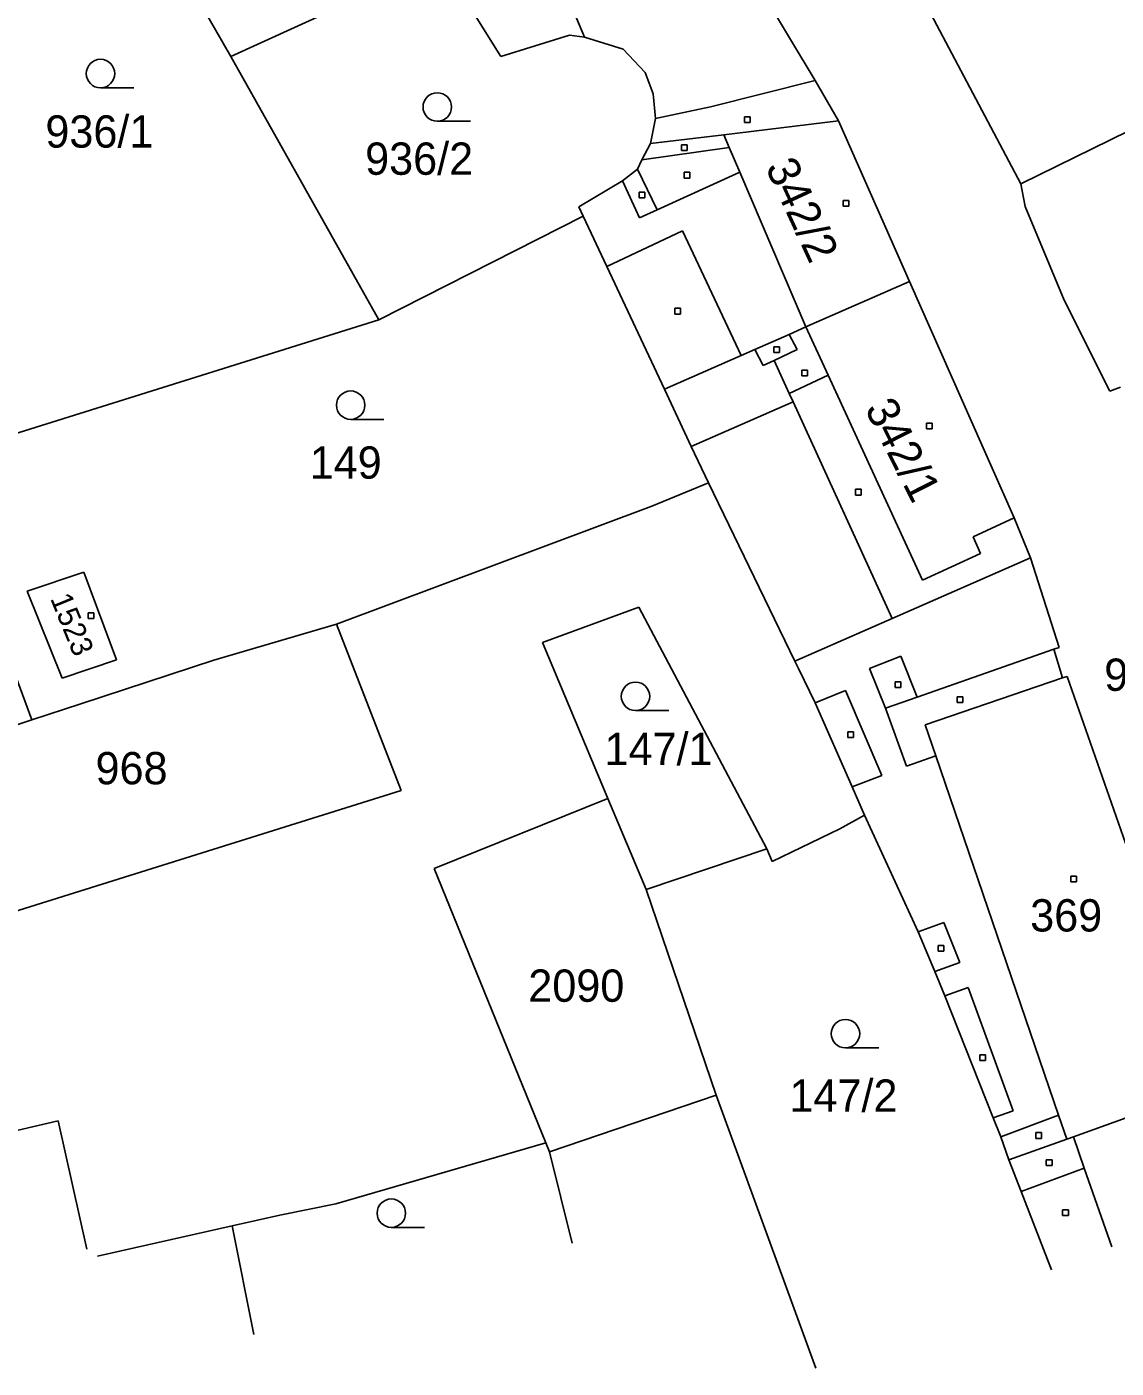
# Model space of a CAD drawing. Extents: x -711879 to -711361, y -1048782 to -1048177.
# Drawn here: x -711759.4 to -711702.1, y -1048728.8 to -1048658.1 of the extents above; entities that cross this region are included whole.
import ezdxf

# ---------------------------------------------------------------- set-up
doc = ezdxf.new("R2010")
doc.units = 0
for name, color, linetype in [('Vrstva 1', 7, 'Continuous'), ('Vrstva 14', 7, 'Continuous'), ('Vrstva 15', 7, 'Continuous'), ('Vrstva 2', 7, 'Continuous'), ('Vrstva 23', 7, 'Continuous'), ('Vrstva 25', 7, 'Continuous'), ('Vrstva 46', 7, 'Continuous')]:
    doc.layers.add(name, color=color, linetype=linetype)

msp = doc.modelspace()

# ---------------------------------------------------------------- linework, layer by layer
at = {"layer": 'Vrstva 1'}
for p, q in [((-711647.12, -1048637.04), (-711707.08, -1048666.39)), ((-711748.69, -1048659.7), (-711756.32, -1048646.29)), ((-711737.61, -1048654.63), (-711748.69, -1048659.7)), ((-711737.61, -1048654.63), (-711734.47, -1048659.69)), ((-711722.03, -1048654.1), (-711717.9, -1048660.95)), ((-711707.08, -1048666.39), (-711712.77, -1048655.63)), ((-711734.47, -1048659.69), (-711730.85, -1048658.57)), ((-711730.85, -1048658.57), (-711730.06, -1048658.68)), ((-711728.02, -1048659.31), (-711730.06, -1048658.68)), ((-711726.86, -1048660.53), (-711728.02, -1048659.31)), ((-711748.69, -1048659.7), (-711740.88, -1048673.56)), ((-711726.43, -1048661.65), (-711726.86, -1048660.53)), ((-711717.9, -1048660.95), (-711716.67, -1048663.08)), ((-711726.32, -1048662.96), (-711726.43, -1048661.65)), ((-711726.58, -1048664.28), (-711726.32, -1048662.96)), ((-711716.67, -1048663.08), (-711722.72, -1048663.81)), ((-711716.67, -1048663.08), (-711712.94, -1048671.54)), ((-711722.72, -1048663.81), (-711726.58, -1048664.28)), ((-711727.03, -1048665.13), (-711726.58, -1048664.28)), ((-711727.26, -1048665.62), (-711727.03, -1048665.13)), ((-711728.06, -1048666.24), (-711727.26, -1048665.62)), ((-711730.35, -1048667.6), (-711728.06, -1048666.24)), ((-711706.84, -1048667.59), (-711707.08, -1048666.39)), ((-711730.12, -1048668.09), (-711740.88, -1048673.56)), ((-711730.12, -1048668.09), (-711730.35, -1048667.6)), ((-711730.12, -1048668.09), (-711728.88, -1048670.74)), ((-711704.79, -1048672.52), (-711706.84, -1048667.59)), ((-711728.88, -1048670.74), (-711725.85, -1048677.2)), ((-711718.39, -1048673.93), (-711712.94, -1048671.54)), ((-711712.94, -1048671.54), (-711707.43, -1048683.98)), ((-711702.39, -1048677.31), (-711704.79, -1048672.52)), ((-711761.8, -1048680.11), (-711740.88, -1048673.56)), ((-711721.09, -1048675.12), (-711719.27, -1048674.32)), ((-711719.27, -1048674.32), (-711718.39, -1048673.93)), ((-711721.81, -1048675.44), (-711721.09, -1048675.12)), ((-711725.85, -1048677.2), (-711721.81, -1048675.44)), ((-711724.43, -1048680.23), (-711725.85, -1048677.2)), ((-711701.82, -1048677.11), (-711702.39, -1048677.31)), ((-711723.53, -1048682.13), (-711724.43, -1048680.23)), ((-711723.53, -1048682.13), (-711726.51, -1048683.36)), ((-711718.98, -1048691.53), (-711723.53, -1048682.13)), ((-711763.42, -1048683.16), (-711759.16, -1048694.62)), ((-711743.11, -1048689.58), (-711726.51, -1048683.36)), ((-711707.43, -1048683.98), (-711706.56, -1048686.09)), ((-711713.85, -1048689.28), (-711706.56, -1048686.09)), ((-711706.56, -1048686.09), (-711705.05, -1048690.8)), ((-711756.42, -1048686.85), (-711759.41, -1048687.84)), ((-711754.71, -1048691.46), (-711756.42, -1048686.85)), ((-711757.57, -1048692.43), (-711759.41, -1048687.84)), ((-711727.2, -1048688.68), (-711732.27, -1048690.54)), ((-711720.45, -1048701.4), (-711727.2, -1048688.68)), ((-711718.98, -1048691.53), (-711713.85, -1048689.28)), ((-711743.11, -1048689.58), (-711749.58, -1048691.48)), ((-711743.11, -1048689.58), (-711739.72, -1048698.33)), ((-711728.82, -1048698.75), (-711732.27, -1048690.54)), ((-711757.57, -1048692.43), (-711754.71, -1048691.46)), ((-711705.05, -1048690.8), (-711705.33, -1048690.9)), ((-711704.88, -1048692.41), (-711705.33, -1048690.9)), ((-711749.58, -1048691.48), (-711756.58, -1048693.78)), ((-711718.98, -1048691.53), (-711718.79, -1048691.92)), ((-711718.79, -1048691.92), (-711717.91, -1048693.72)), ((-711704.64, -1048692.33), (-711704.88, -1048692.41)), ((-711697.07, -1048713.95), (-711704.64, -1048692.33)), ((-711759.16, -1048694.62), (-711756.58, -1048693.78)), ((-711717.91, -1048693.72), (-711715.96, -1048698.15)), ((-711761.13, -1048695.26), (-711759.16, -1048694.62)), ((-711739.72, -1048698.33), (-711764.36, -1048706.06)), ((-711715.96, -1048698.15), (-711715.31, -1048699.64)), ((-711728.82, -1048698.75), (-711737.97, -1048702.44)), ((-711726.8, -1048703.55), (-711728.82, -1048698.75)), ((-711716.6, -1048700.35), (-711715.31, -1048699.64)), ((-711715.31, -1048699.64), (-711712.48, -1048705.78)), ((-711720.17, -1048702.07), (-711716.6, -1048700.35)), ((-711720.45, -1048701.4), (-711726.8, -1048703.55)), ((-711720.45, -1048701.4), (-711720.17, -1048702.07)), ((-711737.97, -1048702.44), (-711732.1, -1048716.88)), ((-711723.12, -1048714.37), (-711726.8, -1048703.55)), ((-711712.48, -1048705.78), (-711711.6, -1048707.86)), ((-711711.6, -1048707.86), (-711711.07, -1048709.14)), ((-711711.07, -1048709.14), (-711708.53, -1048715.57)), ((-711697.07, -1048713.95), (-711704.3, -1048716.57)), ((-711723.12, -1048714.37), (-711731.9, -1048717.36)), ((-711723.12, -1048714.37), (-711717.87, -1048728.75)), ((-711708.53, -1048715.57), (-711708.12, -1048716.57)), ((-711732.1, -1048716.88), (-711743.15, -1048720.09)), ((-711732.1, -1048716.88), (-711731.9, -1048717.36)), ((-711708.12, -1048716.57), (-711707.7, -1048717.78)), ((-711704.65, -1048716.69), (-711707.7, -1048717.78)), ((-711704.3, -1048716.57), (-711704.65, -1048716.69)), ((-711731.9, -1048717.36), (-711730.71, -1048722.16)), ((-711707.7, -1048717.78), (-711707.06, -1048719.44)), ((-711707.06, -1048719.44), (-711705.46, -1048723.58)), ((-711743.15, -1048720.09), (-711746.1, -1048720.7)), ((-711746.1, -1048720.7), (-711748.62, -1048721.26)), ((-711748.62, -1048721.26), (-711755.7, -1048722.85)), ((-711747.48, -1048726.98), (-711748.62, -1048721.26))]:
    msp.add_line(p, q, dxfattribs=at)
at = {"layer": 'Vrstva 2'}
for p, q in [((-711730.06, -1048658.68), (-711734.14, -1048648.9)), ((-711717.9, -1048660.95), (-711723.41, -1048662.34)), ((-711723.41, -1048662.34), (-711726.32, -1048662.96)), ((-711722.43, -1048664.48), (-711722.72, -1048663.81)), ((-711727.03, -1048665.13), (-711722.43, -1048664.48)), ((-711721.87, -1048665.79), (-711722.43, -1048664.48)), ((-711727.26, -1048665.62), (-711726.23, -1048667.77)), ((-711721.87, -1048665.79), (-711726.23, -1048667.77)), ((-711718.39, -1048673.93), (-711721.87, -1048665.79)), ((-711727.15, -1048668.19), (-711728.06, -1048666.24)), ((-711726.23, -1048667.77), (-711727.15, -1048668.19)), ((-711724.89, -1048668.87), (-711728.88, -1048670.74)), ((-711721.81, -1048675.44), (-711724.89, -1048668.87)), ((-711718.86, -1048675.12), (-711719.27, -1048674.32)), ((-711717.22, -1048676.47), (-711718.39, -1048673.93)), ((-711721.09, -1048675.12), (-711720.65, -1048675.96)), ((-711720.06, -1048675.69), (-711718.86, -1048675.12)), ((-711720.65, -1048675.96), (-711720.06, -1048675.69)), ((-711719.27, -1048677.44), (-711720.06, -1048675.69)), ((-711719.27, -1048677.44), (-711717.22, -1048676.47)), ((-711717.22, -1048676.47), (-711712.25, -1048687.26)), ((-711719.07, -1048677.87), (-711724.43, -1048680.23)), ((-711719.07, -1048677.87), (-711719.27, -1048677.44)), ((-711713.85, -1048689.28), (-711719.07, -1048677.87)), ((-711707.43, -1048683.98), (-711709.59, -1048684.98)), ((-711709.59, -1048684.98), (-711709.2, -1048685.86)), ((-711709.2, -1048685.86), (-711712.25, -1048687.26)), ((-711715.04, -1048691.92), (-711713.4, -1048691.27)), ((-711713.4, -1048691.27), (-711712.53, -1048693.42)), ((-711712.53, -1048693.42), (-711705.33, -1048690.9)), ((-711714.2, -1048694.01), (-711715.04, -1048691.92)), ((-711704.88, -1048692.41), (-711712.11, -1048694.88)), ((-711716.31, -1048693.07), (-711717.91, -1048693.72)), ((-711716.31, -1048693.07), (-711714.4, -1048697.54)), ((-711714.2, -1048694.01), (-711712.53, -1048693.42)), ((-711714.2, -1048694.01), (-711713.09, -1048697.06)), ((-711712.11, -1048694.88), (-711711.55, -1048696.51)), ((-711713.09, -1048697.06), (-711711.55, -1048696.51)), ((-711711.55, -1048696.51), (-711705.08, -1048715.43)), ((-711715.96, -1048698.15), (-711714.4, -1048697.54)), ((-711712.48, -1048705.78), (-711711.12, -1048705.29)), ((-711711.12, -1048705.29), (-711710.28, -1048707.39)), ((-711711.6, -1048707.86), (-711710.28, -1048707.39)), ((-711711.07, -1048709.14), (-711709.84, -1048708.71)), ((-711707.47, -1048715.21), (-711709.84, -1048708.71)), ((-711708.53, -1048715.57), (-711707.47, -1048715.21)), ((-711708.12, -1048716.57), (-711705.08, -1048715.43)), ((-711705.08, -1048715.43), (-711704.65, -1048716.69)), ((-711770.07, -1048718.6), (-711757.78, -1048715.73)), ((-711757.78, -1048715.73), (-711756.27, -1048722.49)), ((-711704.3, -1048716.57), (-711703.73, -1048718.22)), ((-711707.06, -1048719.44), (-711703.73, -1048718.22)), ((-711703.73, -1048718.22), (-711702.28, -1048722.36))]:
    msp.add_line(p, q, dxfattribs=at)
at = {"layer": 'Vrstva 23'}
for p, q in [((-711755.55, -1048661.34), (-711753.8, -1048661.34)), ((-711737.81, -1048663.1), (-711736.06, -1048663.1)), ((-711742.37, -1048678.8), (-711740.62, -1048678.8)), ((-711727.37, -1048694.13), (-711725.62, -1048694.13)), ((-711716.31, -1048711.89), (-711714.56, -1048711.89)), ((-711740.23, -1048721.34), (-711738.48, -1048721.34))]:
    msp.add_line(p, q, dxfattribs=at)
for centre in [(-711755.55, -1048660.59), (-711737.81, -1048662.35), (-711742.37, -1048678.05), (-711727.37, -1048693.38), (-711716.31, -1048711.14), (-711740.23, -1048720.59)]:
    msp.add_circle(centre, 0.75, dxfattribs=at)
at = {"layer": 'Vrstva 25'}
for p, q in [((-711721.63, -1048662.86), (-711721.33, -1048662.86)), ((-711721.63, -1048663.16), (-711721.63, -1048662.86)), ((-711721.33, -1048663.16), (-711721.63, -1048663.16)), ((-711721.33, -1048662.86), (-711721.33, -1048663.16)), ((-711724.95, -1048664.34), (-711724.65, -1048664.34)), ((-711724.95, -1048664.64), (-711724.95, -1048664.34)), ((-711724.65, -1048664.34), (-711724.65, -1048664.64)), ((-711724.65, -1048664.64), (-711724.95, -1048664.64)), ((-711724.81, -1048665.79), (-711724.51, -1048665.79)), ((-711724.81, -1048666.09), (-711724.81, -1048665.79)), ((-711724.51, -1048665.79), (-711724.51, -1048666.09)), ((-711724.51, -1048666.09), (-711724.81, -1048666.09)), ((-711727.18, -1048666.83), (-711726.88, -1048666.83)), ((-711727.18, -1048667.13), (-711727.18, -1048666.83)), ((-711726.88, -1048667.13), (-711727.18, -1048667.13)), ((-711726.88, -1048666.83), (-711726.88, -1048667.13)), ((-711716.43, -1048667.28), (-711716.13, -1048667.28)), ((-711716.43, -1048667.58), (-711716.43, -1048667.28)), ((-711716.13, -1048667.28), (-711716.13, -1048667.58)), ((-711716.13, -1048667.58), (-711716.43, -1048667.58)), ((-711725.29, -1048672.95), (-711724.99, -1048672.95)), ((-711725.29, -1048673.25), (-711725.29, -1048672.95)), ((-711724.99, -1048672.95), (-711724.99, -1048673.25)), ((-711724.99, -1048673.25), (-711725.29, -1048673.25)), ((-711720.09, -1048674.98), (-711719.79, -1048674.98)), ((-711720.09, -1048675.28), (-711720.09, -1048674.98)), ((-711719.79, -1048674.98), (-711719.79, -1048675.28)), ((-711719.79, -1048675.28), (-711720.09, -1048675.28)), ((-711718.61, -1048676.21), (-711718.31, -1048676.21)), ((-711718.61, -1048676.51), (-711718.61, -1048676.21)), ((-711718.31, -1048676.51), (-711718.61, -1048676.51)), ((-711718.31, -1048676.21), (-711718.31, -1048676.51)), ((-711712.05, -1048679), (-711711.75, -1048679)), ((-711712.05, -1048679.3), (-711712.05, -1048679)), ((-711711.75, -1048679.3), (-711712.05, -1048679.3)), ((-711711.75, -1048679), (-711711.75, -1048679.3)), ((-711715.78, -1048682.48), (-711715.48, -1048682.48)), ((-711715.78, -1048682.78), (-711715.78, -1048682.48)), ((-711715.48, -1048682.78), (-711715.78, -1048682.78)), ((-711715.48, -1048682.48), (-711715.48, -1048682.78)), ((-711756.2, -1048688.98), (-711755.9, -1048688.98)), ((-711756.2, -1048689.28), (-711756.2, -1048688.98)), ((-711755.9, -1048689.28), (-711756.2, -1048689.28)), ((-711755.9, -1048688.98), (-711755.9, -1048689.28)), ((-711713.7, -1048692.62), (-711713.4, -1048692.62)), ((-711713.7, -1048692.92), (-711713.7, -1048692.62)), ((-711713.4, -1048692.62), (-711713.4, -1048692.92)), ((-711713.4, -1048692.92), (-711713.7, -1048692.92)), ((-711710.43, -1048693.41), (-711710.13, -1048693.41)), ((-711710.43, -1048693.71), (-711710.43, -1048693.41)), ((-711710.13, -1048693.41), (-711710.13, -1048693.71)), ((-711710.13, -1048693.71), (-711710.43, -1048693.71)), ((-711716.18, -1048695.25), (-711715.88, -1048695.25)), ((-711716.18, -1048695.55), (-711716.18, -1048695.25)), ((-711715.88, -1048695.55), (-711716.18, -1048695.55)), ((-711715.88, -1048695.25), (-711715.88, -1048695.55)), ((-711704.44, -1048702.84), (-711704.14, -1048702.84)), ((-711704.44, -1048703.14), (-711704.44, -1048702.84)), ((-711704.14, -1048703.14), (-711704.44, -1048703.14)), ((-711704.14, -1048702.84), (-711704.14, -1048703.14)), ((-711711.42, -1048706.5), (-711711.12, -1048706.5)), ((-711711.42, -1048706.8), (-711711.42, -1048706.5)), ((-711711.12, -1048706.8), (-711711.42, -1048706.8)), ((-711711.12, -1048706.5), (-711711.12, -1048706.8)), ((-711709.24, -1048712.26), (-711708.94, -1048712.26)), ((-711709.24, -1048712.56), (-711709.24, -1048712.26)), ((-711708.94, -1048712.56), (-711709.24, -1048712.56)), ((-711708.94, -1048712.26), (-711708.94, -1048712.56)), ((-711706.28, -1048716.35), (-711705.98, -1048716.35)), ((-711706.28, -1048716.65), (-711706.28, -1048716.35)), ((-711705.98, -1048716.65), (-711706.28, -1048716.65)), ((-711705.98, -1048716.35), (-711705.98, -1048716.65)), ((-711705.73, -1048717.78), (-711705.43, -1048717.78)), ((-711705.73, -1048718.08), (-711705.73, -1048717.78)), ((-711705.43, -1048718.08), (-711705.73, -1048718.08)), ((-711705.43, -1048717.78), (-711705.43, -1048718.08)), ((-711704.87, -1048720.42), (-711704.57, -1048720.42)), ((-711704.87, -1048720.72), (-711704.87, -1048720.42)), ((-711704.57, -1048720.72), (-711704.87, -1048720.72)), ((-711704.57, -1048720.42), (-711704.57, -1048720.72))]:
    msp.add_line(p, q, dxfattribs=at)
at = {"layer": 'Vrstva 46'}
for p, q in [((-711730.06, -1048658.68), (-711730.06, -1048658.68)), ((-711728.02, -1048659.31), (-711728.02, -1048659.31)), ((-711748.69, -1048659.7), (-711748.69, -1048659.7)), ((-711726.86, -1048660.53), (-711726.86, -1048660.53)), ((-711740.88, -1048673.56), (-711740.88, -1048673.56)), ((-711726.51, -1048683.36), (-711726.51, -1048683.36)), ((-711743.11, -1048689.58), (-711743.11, -1048689.58)), ((-711749.58, -1048691.48), (-711749.58, -1048691.48)), ((-711754.95, -1048693.24), (-711754.95, -1048693.24)), ((-711720.45, -1048701.4), (-711720.45, -1048701.4)), ((-711726.8, -1048703.55), (-711726.8, -1048703.55)), ((-711723.12, -1048714.37), (-711723.12, -1048714.37)), ((-711743.15, -1048720.09), (-711743.15, -1048720.09)), ((-711746.1, -1048720.7), (-711746.1, -1048720.7))]:
    msp.add_line(p, q, dxfattribs=at)

# ---------------------------------------------------------------- texts
at = {"layer": 'Vrstva 14'}
for s, p in [('936/1', (-711758.453, -1048664.49)), ('936/2', (-711741.61, -1048665.92)), ('149', (-711744.53, -1048681.92)), ('919/7', (-711702.68, -1048693.09)), ('147/1', (-711729, -1048697)), ('968', (-711755.81, -1048698.01)), ('2090', (-711733.015, -1048709.46)), ('147/2', (-711719.26, -1048715.25))]:
    msp.add_text(s, height=1.7, dxfattribs=at).set_placement(p)
at = {"layer": 'Vrstva 15'}
for s, height, rotation, p in [('342/2', 1.7, 294.84081, (-711720.55, -1048665.52)), ('342/1', 1.7, 296.88957, (-711715.32, -1048678.23)), ('1523', 1.14, 292.34061, (-711758.21, -1048688.226))]:
    msp.add_text(s, height=height, rotation=rotation, dxfattribs=at).set_placement(p)
msp.add_text('369', height=1.7, dxfattribs=at).set_placement((-711706.58, -1048705.76))

doc.saveas('drawing.dxf')
